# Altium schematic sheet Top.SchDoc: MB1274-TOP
size A3; Date: 3/31/2015; Author: P.A.; CompanyName: STMicroelectronics; Organization: Microcontrollers Division; Address1: 12, Rue Jules HOROWITZ; Address2: 38019 Grenoble; Address3: FRANCE; DocumentNumber: 2; Revision: D-01; SheetNumber: 2; SheetTotal: 12; Project: STM32F413H-DISCO
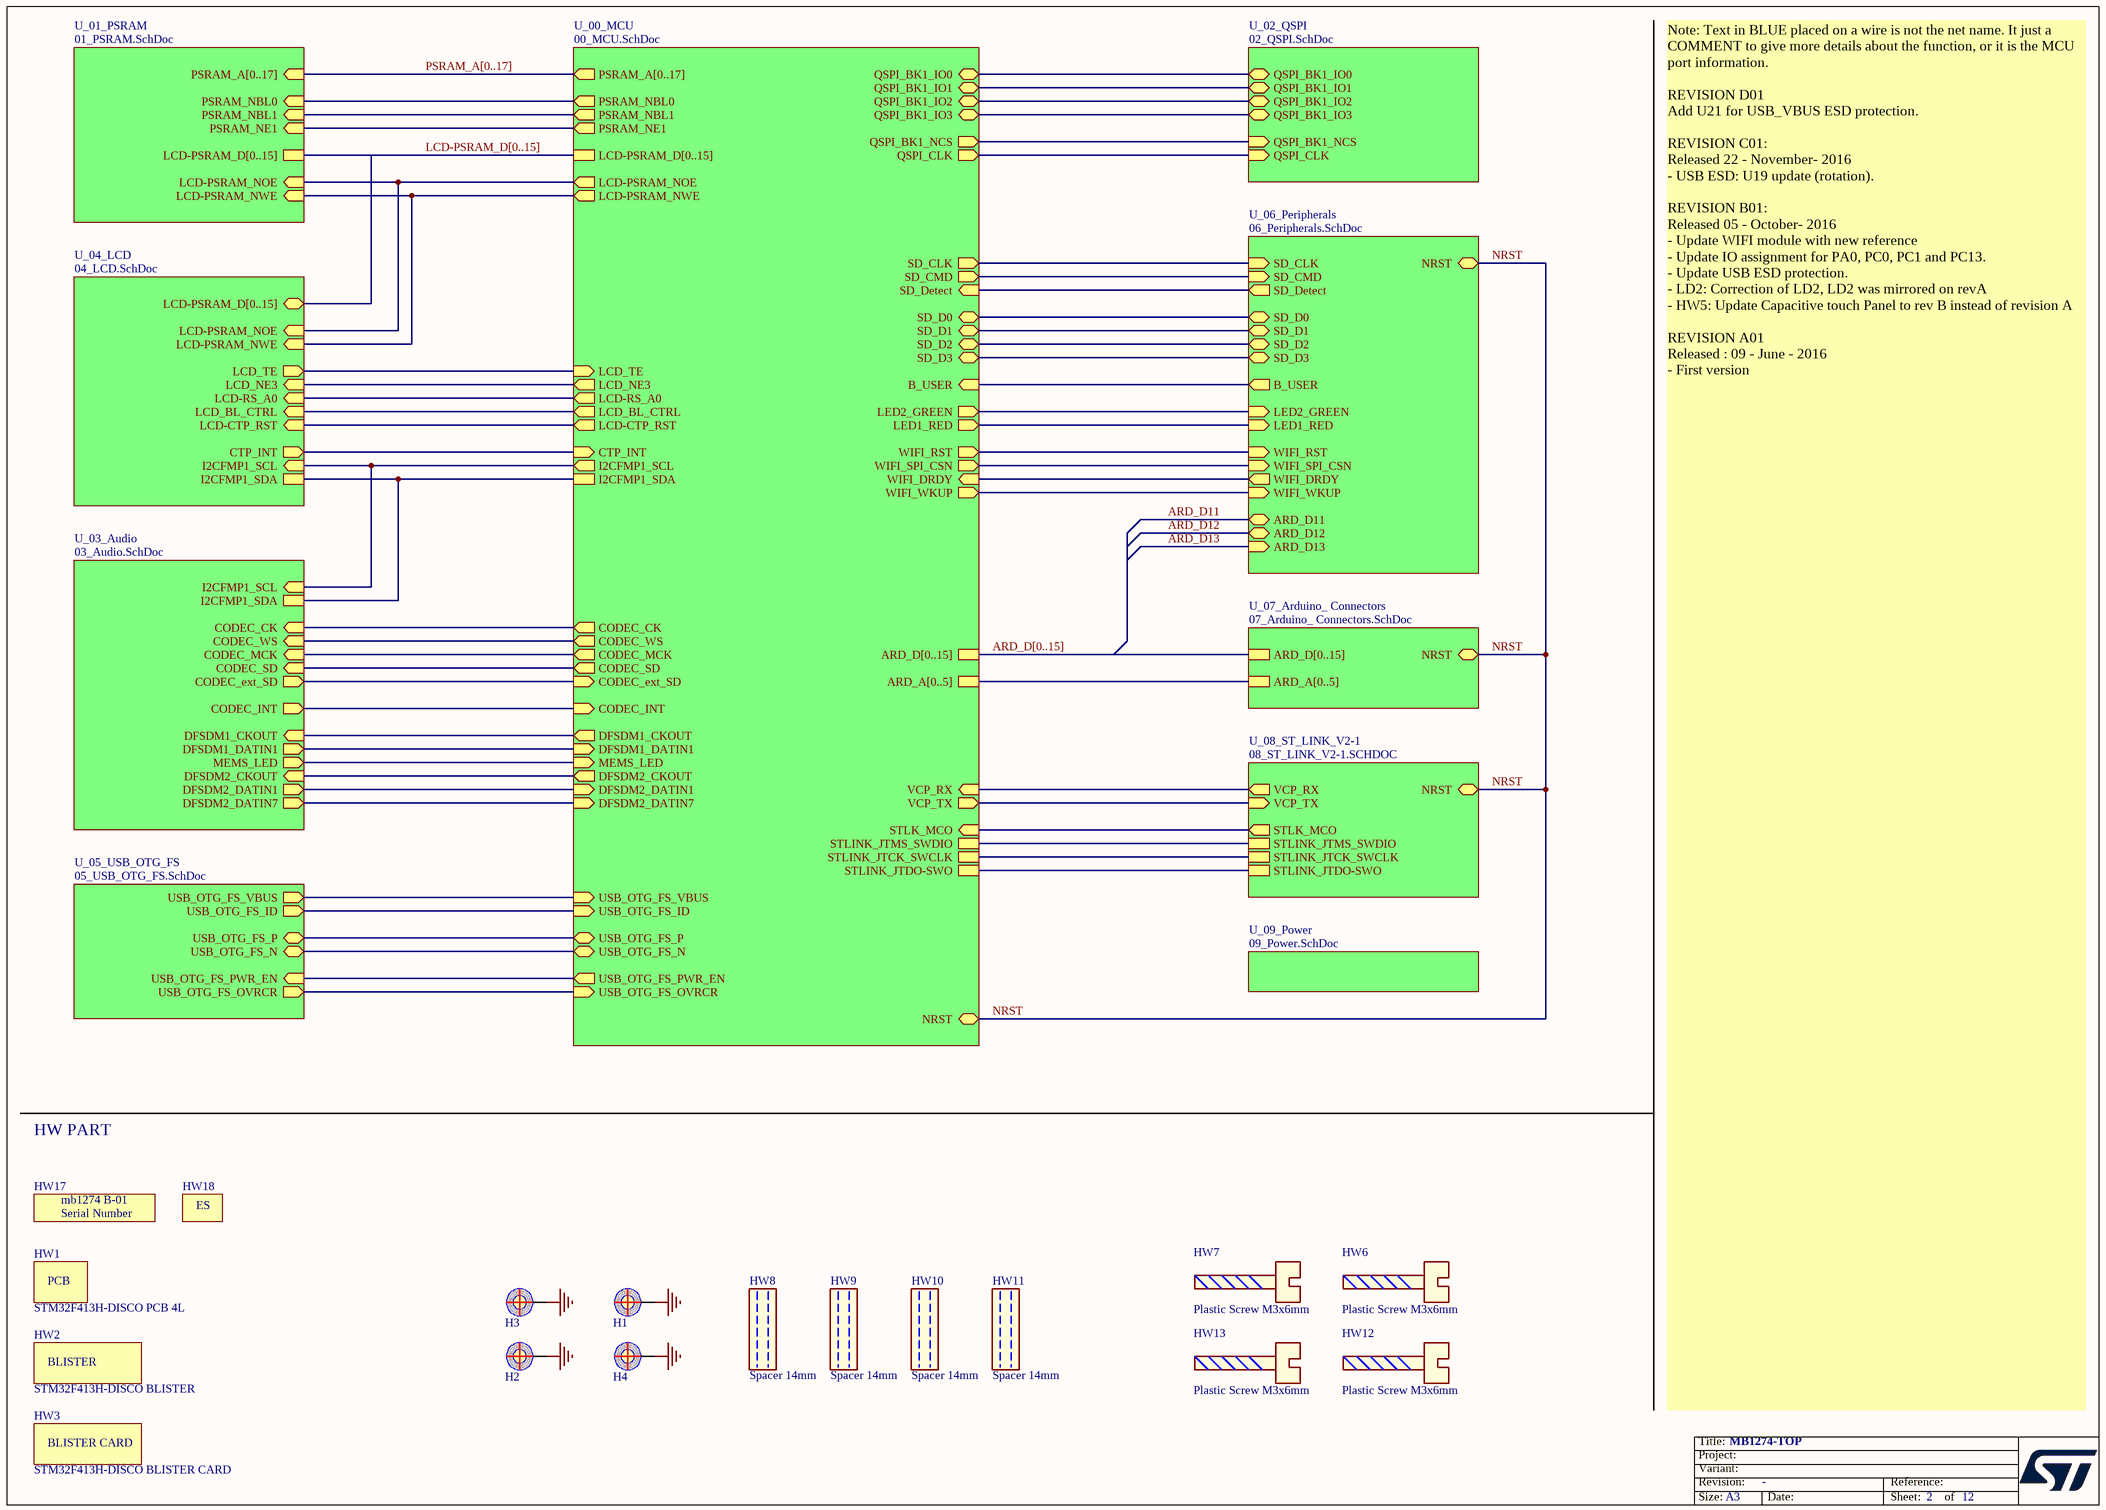
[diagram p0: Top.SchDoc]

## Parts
H1  POSITION HOLE C6D3R5  [PTH_M1261-3005-N_3P5X6_M3_H14]  (value not drawn)
H2  POSITION HOLE C6D3R5  [PTH_M1261-3005-N_3P5X6_M3_H14]  (value not drawn)
H3  POSITION HOLE C6D3R5  [PTH_M1261-3005-N_3P5X6_M3_H14]  (value not drawn)
H4  POSITION HOLE C6D3R5  [PTH_M1261-3005-N_3P5X6_M3_H14]  (value not drawn)
HW1  STM32F413H-DISCO PCB 4L  (mechanical)
HW2  STM32F413H-DISCO BLISTER  (mechanical)
HW3  STM32F413H-DISCO BLISTER CARD  (mechanical)
HW6  Plastic Screw M3x6mm  (mechanical)
HW7  Plastic Screw M3x6mm  (mechanical)
HW8  Spacer 14mm  (mechanical)
HW9  Spacer 14mm  (mechanical)
HW10  Spacer 14mm  (mechanical)
HW11  Spacer 14mm  (mechanical)
HW12  Plastic Screw M3x6mm  (mechanical)
HW13  Plastic Screw M3x6mm  (mechanical)
HW17  mb1274 B-01 + SN  (value not drawn)  (mechanical)
HW18  ES  (value not drawn)  (mechanical)

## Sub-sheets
U_00_MCU = 00_MCU.SchDoc: NRST (bidir), QSPI_BK1_IO3 (bidir), QSPI_BK1_IO2 (bidir), QSPI_BK1_IO0 (bidir), QSPI_BK1_IO1 (bidir), QSPI_CLK (out), QSPI_BK1_NCS (out), USB_OTG_FS_OVRCR (in), USB_OTG_FS_PWR_EN (out), B_USER (in), STLK_MCO (in), CODEC_INT (in), LCD_TE (in), LCD_BL_CTRL (out), PSRAM_A[0..17] (out), LCD-PSRAM_D[0..15], LCD-PSRAM_NWE (out), LCD-PSRAM_NOE (out), PSRAM_NE1 (out), PSRAM_NBL0 (out), PSRAM_NBL1 (out), LCD_NE3 (out), LCD-CTP_RST (out), CTP_INT (in), LED1_RED (out), LED2_GREEN (out), USB_OTG_FS_VBUS (in), USB_OTG_FS_ID (in), I2CFMP1_SDA, I2CFMP1_SCL (out), USB_OTG_FS_N (bidir), USB_OTG_FS_P (bidir), STLINK_JTMS_SWDIO, STLINK_JTCK_SWCLK, STLINK_JTDO-SWO, LCD-RS_A0 (out), SD_D2 (bidir), WIFI_SPI_CSN (out), DFSDM2_DATIN7 (in), WIFI_DRDY (in), SD_D3 (bidir), SD_CLK (out), DFSDM1_DATIN1 (in), DFSDM2_DATIN1 (in), DFSDM1_CKOUT (out), SD_Detect (in), SD_CMD (out), SD_D0 (bidir), SD_D1 (bidir), DFSDM2_CKOUT (out), CODEC_WS (out), CODEC_CK (out), CODEC_SD (out), CODEC_MCK (out), CODEC_ext_SD (in), ARD_A[0..5], ARD_D[0..15], VCP_TX (out), VCP_RX (in), WIFI_WKUP (out), MEMS_LED (in), WIFI_RST (out)
U_01_PSRAM = 01_PSRAM.SchDoc: PSRAM_A[0..17] (in), LCD-PSRAM_D[0..15], LCD-PSRAM_NWE (in), LCD-PSRAM_NOE (in), PSRAM_NE1 (in), PSRAM_NBL0 (in), PSRAM_NBL1 (in)
U_02_QSPI = 02_QSPI.SchDoc: QSPI_BK1_IO0 (bidir), QSPI_BK1_IO2 (bidir), QSPI_BK1_IO1 (bidir), QSPI_BK1_IO3 (bidir), QSPI_CLK (in), QSPI_BK1_NCS (in)
U_03_Audio = 03_Audio.SchDoc: CODEC_INT (out), I2CFMP1_SCL (in), I2CFMP1_SDA, DFSDM1_DATIN1 (out), DFSDM1_CKOUT (in), DFSDM2_CKOUT (in), DFSDM2_DATIN1 (out), DFSDM2_DATIN7 (out), CODEC_CK (in), CODEC_WS (in), CODEC_SD (in), CODEC_ext_SD (out), CODEC_MCK (in), MEMS_LED (out)
U_04_LCD = 04_LCD.SchDoc: LCD_BL_CTRL (in), CTP_INT (out), LCD_TE (out), LCD-CTP_RST (in), LCD_NE3 (in), LCD-PSRAM_D[0..15] (bidir), LCD-PSRAM_NWE (in), LCD-PSRAM_NOE (in), LCD-RS_A0 (in), I2CFMP1_SDA, I2CFMP1_SCL (in)
U_05_USB_OTG_FS = 05_USB_OTG_FS.SchDoc: USB_OTG_FS_VBUS (out), USB_OTG_FS_ID (out), USB_OTG_FS_PWR_EN (in), USB_OTG_FS_OVRCR (out), USB_OTG_FS_N (bidir), USB_OTG_FS_P (bidir)
U_06_Peripherals = 06_Peripherals.SchDoc: LED1_RED (in), LED2_GREEN (in), NRST (bidir), B_USER (out), SD_CLK (in), SD_CMD (in), SD_D0 (bidir), SD_D1 (bidir), SD_D2 (bidir), SD_D3 (bidir), SD_Detect (out), WIFI_SPI_CSN (in), WIFI_DRDY (out), WIFI_RST (in), WIFI_WKUP (in), ARD_D11 (bidir), ARD_D12 (bidir), ARD_D13 (in)
U_07_Arduino_ Connectors = 07_Arduino_ Connectors.SchDoc: NRST (bidir), ARD_A[0..5], ARD_D[0..15]
U_08_ST_LINK_V2-1 = 08_ST_LINK_V2-1.SCHDOC: NRST (bidir), STLINK_JTDO-SWO, STLK_MCO (out), STLINK_JTMS_SWDIO, STLINK_JTCK_SWCLK, VCP_RX (out), VCP_TX (in)
U_09_Power = 09_Power.SchDoc: no entries

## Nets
GND: H1.1 H2.1 H3.1 H4.1
NRST: sheet U_00_MCU/NRST, sheet U_06_Peripherals/NRST, sheet U_07_Arduino_ Connectors/NRST, sheet U_08_ST_LINK_V2-1/NRST
(unnamed): sheet U_00_MCU/QSPI_BK1_IO3, sheet U_02_QSPI/QSPI_BK1_IO3
(unnamed): sheet U_00_MCU/QSPI_BK1_IO2, sheet U_02_QSPI/QSPI_BK1_IO2  [a separate net that carries the same name]
(unnamed): sheet U_00_MCU/QSPI_BK1_IO0, sheet U_02_QSPI/QSPI_BK1_IO0  [a separate net that carries the same name]
(unnamed): sheet U_00_MCU/QSPI_BK1_IO1, sheet U_02_QSPI/QSPI_BK1_IO1  [a separate net that carries the same name]
(unnamed): sheet U_00_MCU/QSPI_CLK, sheet U_02_QSPI/QSPI_CLK  [a separate net that carries the same name]
(unnamed): sheet U_00_MCU/QSPI_BK1_NCS, sheet U_02_QSPI/QSPI_BK1_NCS  [a separate net that carries the same name]
(unnamed): sheet U_00_MCU/USB_OTG_FS_OVRCR, sheet U_05_USB_OTG_FS/USB_OTG_FS_OVRCR  [a separate net that carries the same name]
(unnamed): sheet U_00_MCU/USB_OTG_FS_PWR_EN, sheet U_05_USB_OTG_FS/USB_OTG_FS_PWR_EN  [a separate net that carries the same name]
(unnamed): sheet U_00_MCU/B_USER, sheet U_06_Peripherals/B_USER  [a separate net that carries the same name]
(unnamed): sheet U_00_MCU/STLK_MCO, sheet U_08_ST_LINK_V2-1/STLK_MCO  [a separate net that carries the same name]
(unnamed): sheet U_00_MCU/CODEC_INT, sheet U_03_Audio/CODEC_INT  [a separate net that carries the same name]
(unnamed): sheet U_00_MCU/LCD_TE, sheet U_04_LCD/LCD_TE  [a separate net that carries the same name]
(unnamed): sheet U_00_MCU/LCD_BL_CTRL, sheet U_04_LCD/LCD_BL_CTRL  [a separate net that carries the same name]
(unnamed): sheet U_00_MCU/LCD-PSRAM_NWE, sheet U_01_PSRAM/LCD-PSRAM_NWE, sheet U_04_LCD/LCD-PSRAM_NWE  [a separate net that carries the same name]
(unnamed): sheet U_00_MCU/LCD-PSRAM_NOE, sheet U_01_PSRAM/LCD-PSRAM_NOE, sheet U_04_LCD/LCD-PSRAM_NOE  [a separate net that carries the same name]
(unnamed): sheet U_00_MCU/PSRAM_NE1, sheet U_01_PSRAM/PSRAM_NE1  [a separate net that carries the same name]
(unnamed): sheet U_00_MCU/PSRAM_NBL0, sheet U_01_PSRAM/PSRAM_NBL0  [a separate net that carries the same name]
(unnamed): sheet U_00_MCU/PSRAM_NBL1, sheet U_01_PSRAM/PSRAM_NBL1  [a separate net that carries the same name]
(unnamed): sheet U_00_MCU/LCD_NE3, sheet U_04_LCD/LCD_NE3  [a separate net that carries the same name]
(unnamed): sheet U_00_MCU/LCD-CTP_RST, sheet U_04_LCD/LCD-CTP_RST  [a separate net that carries the same name]
(unnamed): sheet U_00_MCU/CTP_INT, sheet U_04_LCD/CTP_INT  [a separate net that carries the same name]
(unnamed): sheet U_00_MCU/LED1_RED, sheet U_06_Peripherals/LED1_RED  [a separate net that carries the same name]
(unnamed): sheet U_00_MCU/LED2_GREEN, sheet U_06_Peripherals/LED2_GREEN  [a separate net that carries the same name]
(unnamed): sheet U_00_MCU/USB_OTG_FS_VBUS, sheet U_05_USB_OTG_FS/USB_OTG_FS_VBUS  [a separate net that carries the same name]
(unnamed): sheet U_00_MCU/USB_OTG_FS_ID, sheet U_05_USB_OTG_FS/USB_OTG_FS_ID  [a separate net that carries the same name]
(unnamed): sheet U_00_MCU/I2CFMP1_SDA, sheet U_04_LCD/I2CFMP1_SDA, sheet U_03_Audio/I2CFMP1_SDA  [a separate net that carries the same name]
(unnamed): sheet U_00_MCU/I2CFMP1_SCL, sheet U_04_LCD/I2CFMP1_SCL, sheet U_03_Audio/I2CFMP1_SCL  [a separate net that carries the same name]
(unnamed): sheet U_00_MCU/USB_OTG_FS_N, sheet U_05_USB_OTG_FS/USB_OTG_FS_N  [a separate net that carries the same name]
(unnamed): sheet U_00_MCU/USB_OTG_FS_P, sheet U_05_USB_OTG_FS/USB_OTG_FS_P  [a separate net that carries the same name]
(unnamed): sheet U_00_MCU/STLINK_JTMS_SWDIO, sheet U_08_ST_LINK_V2-1/STLINK_JTMS_SWDIO  [a separate net that carries the same name]
(unnamed): sheet U_00_MCU/STLINK_JTCK_SWCLK, sheet U_08_ST_LINK_V2-1/STLINK_JTCK_SWCLK  [a separate net that carries the same name]
(unnamed): sheet U_00_MCU/STLINK_JTDO-SWO, sheet U_08_ST_LINK_V2-1/STLINK_JTDO-SWO  [a separate net that carries the same name]
(unnamed): sheet U_00_MCU/LCD-RS_A0, sheet U_04_LCD/LCD-RS_A0  [a separate net that carries the same name]
(unnamed): sheet U_00_MCU/SD_D2, sheet U_06_Peripherals/SD_D2  [a separate net that carries the same name]
(unnamed): sheet U_00_MCU/WIFI_SPI_CSN, sheet U_06_Peripherals/WIFI_SPI_CSN  [a separate net that carries the same name]
(unnamed): sheet U_00_MCU/DFSDM2_DATIN7, sheet U_03_Audio/DFSDM2_DATIN7  [a separate net that carries the same name]
(unnamed): sheet U_00_MCU/WIFI_DRDY, sheet U_06_Peripherals/WIFI_DRDY  [a separate net that carries the same name]
(unnamed): sheet U_00_MCU/SD_D3, sheet U_06_Peripherals/SD_D3  [a separate net that carries the same name]
(unnamed): sheet U_00_MCU/SD_CLK, sheet U_06_Peripherals/SD_CLK  [a separate net that carries the same name]
(unnamed): sheet U_00_MCU/DFSDM1_DATIN1, sheet U_03_Audio/DFSDM1_DATIN1  [a separate net that carries the same name]
(unnamed): sheet U_00_MCU/DFSDM2_DATIN1, sheet U_03_Audio/DFSDM2_DATIN1  [a separate net that carries the same name]
(unnamed): sheet U_00_MCU/DFSDM1_CKOUT, sheet U_03_Audio/DFSDM1_CKOUT  [a separate net that carries the same name]
(unnamed): sheet U_00_MCU/SD_Detect, sheet U_06_Peripherals/SD_Detect  [a separate net that carries the same name]
(unnamed): sheet U_00_MCU/SD_CMD, sheet U_06_Peripherals/SD_CMD  [a separate net that carries the same name]
(unnamed): sheet U_00_MCU/SD_D0, sheet U_06_Peripherals/SD_D0  [a separate net that carries the same name]
(unnamed): sheet U_00_MCU/SD_D1, sheet U_06_Peripherals/SD_D1  [a separate net that carries the same name]
(unnamed): sheet U_00_MCU/DFSDM2_CKOUT, sheet U_03_Audio/DFSDM2_CKOUT  [a separate net that carries the same name]
(unnamed): sheet U_00_MCU/CODEC_WS, sheet U_03_Audio/CODEC_WS  [a separate net that carries the same name]
(unnamed): sheet U_00_MCU/CODEC_CK, sheet U_03_Audio/CODEC_CK  [a separate net that carries the same name]
(unnamed): sheet U_00_MCU/CODEC_SD, sheet U_03_Audio/CODEC_SD  [a separate net that carries the same name]
(unnamed): sheet U_00_MCU/CODEC_MCK, sheet U_03_Audio/CODEC_MCK  [a separate net that carries the same name]
(unnamed): sheet U_00_MCU/CODEC_ext_SD, sheet U_03_Audio/CODEC_ext_SD  [a separate net that carries the same name]
(unnamed): sheet U_00_MCU/VCP_TX, sheet U_08_ST_LINK_V2-1/VCP_TX  [a separate net that carries the same name]
(unnamed): sheet U_00_MCU/VCP_RX, sheet U_08_ST_LINK_V2-1/VCP_RX  [a separate net that carries the same name]
(unnamed): sheet U_00_MCU/WIFI_WKUP, sheet U_06_Peripherals/WIFI_WKUP  [a separate net that carries the same name]
(unnamed): sheet U_00_MCU/MEMS_LED, sheet U_03_Audio/MEMS_LED  [a separate net that carries the same name]
(unnamed): sheet U_00_MCU/WIFI_RST, sheet U_06_Peripherals/WIFI_RST  [a separate net that carries the same name]

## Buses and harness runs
bus ARD_D[0..15] = sheet U_00_MCU/ARD_D[0..15] = sheet U_07_Arduino_ Connectors/ARD_D[0..15]
bus LCD-PSRAM_D[0..15] = sheet U_00_MCU/LCD-PSRAM_D[0..15] = sheet U_01_PSRAM/LCD-PSRAM_D[0..15] = sheet U_04_LCD/LCD-PSRAM_D[0..15]
bus PSRAM_A[0..17] = sheet U_00_MCU/PSRAM_A[0..17] = sheet U_01_PSRAM/PSRAM_A[0..17]
bus sheet U_00_MCU/ARD_A[0..5] = sheet U_07_Arduino_ Connectors/ARD_A[0..5]

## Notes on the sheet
- HW PART
- Note: Text in BLUE placed on a wire is not the net name. It just a COMMENT to give more details about the function, or it is the MCU port information.
  REVISION D01
  Add U21 for USB_VBUS ESD protection.
  REVISION C01:
  Released 22 - November- 2016
  - USB ESD: U19 update (rotation).
  REVISION B01:
  Released 05 - October- 2016
  - Update WIFI module with new reference
  - Update IO assignment for PA0, PC0, PC1 and PC13.
  - Update USB ESD protection.
  - LD2: Correction of LD2, LD2 was mirrored on revA
  - HW5: Update Capacitive touch Panel to rev B instead of revision A
  REVISION A01
  Released : 09 - June - 2016
  - First version

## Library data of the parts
HW1 = PCB: Fitted: YES; Ordered_By: Subcon
HW2 = BLISTER: Fitted: YES; Ordered_By: Subcon
HW3 = BLISTER CARD: Ordered_By: subcon; Fitted: YES
HW6 HW7 HW12 HW13 = Plastic Screw M3x6mm: Plastic screw; Ordered_By: Subcon; Fitted: Manually
HW8-HW11 = Plastic Spacer D4.5x14, M3x0.5: Plastic spacer; Manuf_1: RAF; Manuf_Part_1: M1261-3005-N; Ordered_By: Subcon; Fitted: Manually
HW17 = STICKER_SN_number: Sticker for Board SN number; Ordered_By: Subcon; Fitted: YES
HW18 = STICKER_ES: Sticker for ES sample; Ordered_By: Subcon; Fitted: YES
